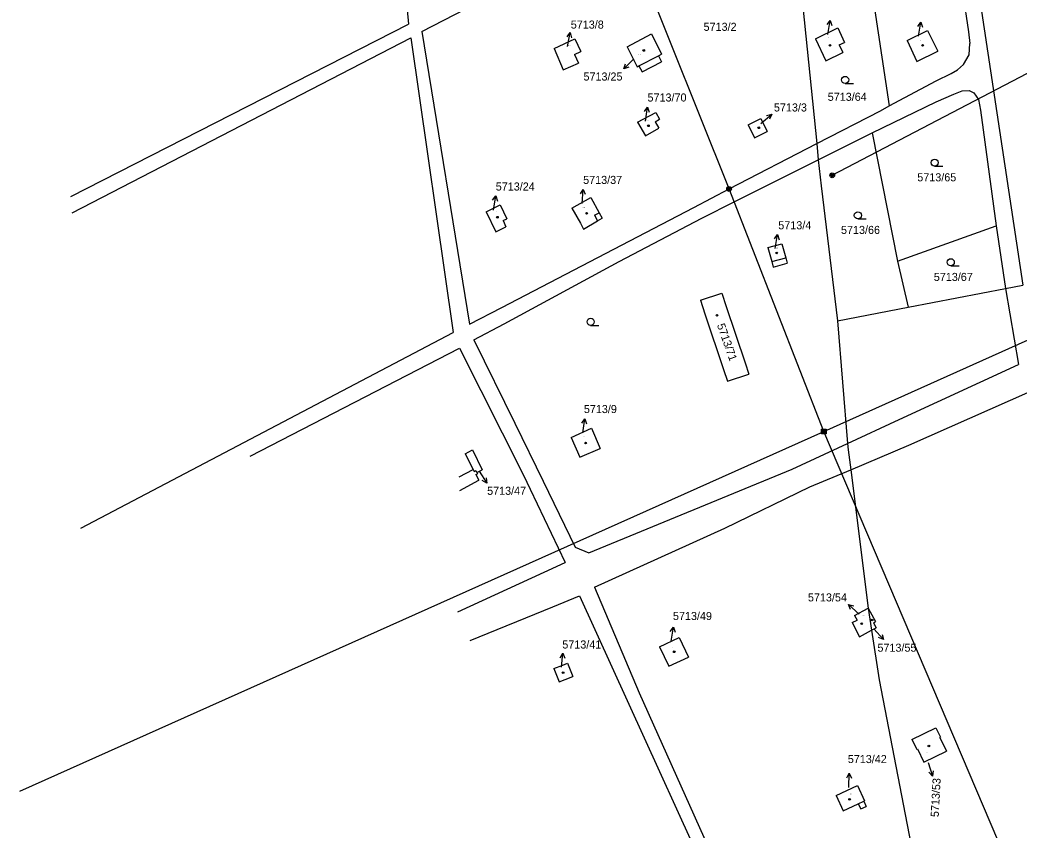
# Model space of a CAD drawing. Extents: x -735092 to -733385, y -1122435 to -1118992.
# Drawn here: x -734530.2 to -734319.7, y -1121420.4 to -1121249.7 of the extents above; entities that cross this region are included whole.
import ezdxf

# ---------------------------------------------------------------- set-up
doc = ezdxf.new("R2010")
doc.units = 0
for name, color, linetype in [('Vrstva 1', 7, 'Continuous'), ('Vrstva 12', 7, 'Continuous'), ('Vrstva 16', 7, 'Continuous'), ('Vrstva 18', 7, 'Continuous'), ('Vrstva 19', 7, 'Continuous'), ('Vrstva 25', 7, 'Continuous'), ('Vrstva 4', 7, 'Continuous')]:
    doc.layers.add(name, color=color, linetype=linetype)

msp = doc.modelspace()

# ---------------------------------------------------------------- linework, layer by layer
at = {"layer": 'Vrstva 1'}
for points in [[(-734339.29, -1121169.94), (-734318.83, -1121305.55)], [(-734333.92, -1121228.08), (-734330.31, -1121252.15)], [(-734351.7, -1121236.91), (-734347.03, -1121267.76)], [(-734365.53, -1121244.07), (-734362.31, -1121275.71)], [(-734362.57, -1121253.65), (-734357.87, -1121251.31)], [(-734357.87, -1121251.31), (-734356.45, -1121254.42)], [(-734417.66, -1121255.71), (-734413.26, -1121253.63)], [(-734413.26, -1121253.63), (-734412, -1121256.33)], [(-734402.24, -1121255.3), (-734397.14, -1121252.57)], [(-734397.14, -1121252.57), (-734394.99, -1121256.88)], [(-734362.57, -1121253.65), (-734360.41, -1121258.28)], [(-734343.21, -1121254.02), (-734338.94, -1121251.9)], [(-734338.94, -1121251.9), (-734336.78, -1121256.22)], [(-734330.31, -1121252.15), (-734330.04, -1121254.64)], [(-734417.66, -1121255.71), (-734415.71, -1121260.15)], [(-734402.24, -1121255.3), (-734400.12, -1121259.53)], [(-734357.55, -1121254.94), (-734356.45, -1121254.42)], [(-734357.55, -1121254.94), (-734356.78, -1121256.52)], [(-734343.21, -1121254.02), (-734341.18, -1121258.43)], [(-734330.16, -1121257.02), (-734330.04, -1121254.64)], [(-734413.32, -1121256.95), (-734412, -1121256.33)], [(-734413.32, -1121256.95), (-734412.49, -1121258.74)], [(-734395.68, -1121257.23), (-734394.99, -1121256.88)], [(-734395.68, -1121257.23), (-734395.03, -1121258.49)], [(-734360.41, -1121258.28), (-734356.78, -1121256.52)], [(-734341.18, -1121258.43), (-734336.78, -1121256.22)], [(-734331.39, -1121259.08), (-734330.16, -1121257.02)], [(-734415.71, -1121260.15), (-734412.49, -1121258.74)], [(-734400.12, -1121259.53), (-734399.76, -1121259.35)], [(-734399.76, -1121259.35), (-734399.12, -1121260.58)], [(-734399.12, -1121260.58), (-734395.03, -1121258.49)], [(-734332.61, -1121260.16), (-734331.39, -1121259.08)], [(-734337.15, -1121262.5), (-734333.96, -1121260.96)], [(-734333.96, -1121260.96), (-734332.61, -1121260.16)], [(-734347.03, -1121267.76), (-734337.15, -1121262.5)], [(-734337.1, -1121266.93), (-734333.42, -1121265.31)], [(-734333.42, -1121265.31), (-734331.61, -1121264.64)], [(-734331.61, -1121264.64), (-734330.18, -1121264.55)], [(-734330.18, -1121264.55), (-734329.17, -1121265.05)], [(-734329.17, -1121265.05), (-734328.19, -1121266.44)], [(-734350.61, -1121273.46), (-734337.1, -1121266.93)], [(-734348.87, -1121268.81), (-734347.03, -1121267.76)], [(-734328.19, -1121266.44), (-734327.75, -1121268.66)], [(-734400.04, -1121271.2), (-734396.18, -1121269.18)], [(-734396.18, -1121269.18), (-734395.41, -1121270.57)], [(-734376.78, -1121271.78), (-734374.05, -1121270.44)], [(-734374.05, -1121270.44), (-734372.71, -1121273.18)], [(-734362.31, -1121275.71), (-734348.87, -1121268.81)], [(-734327.75, -1121268.66), (-734324.5, -1121293.09)], [(-734400.04, -1121271.2), (-734398.42, -1121274.09)], [(-734398.42, -1121274.09), (-734395.59, -1121272.5)], [(-734396.33, -1121271.11), (-734395.41, -1121270.57)], [(-734396.33, -1121271.11), (-734395.59, -1121272.5)], [(-734376.78, -1121271.78), (-734375.44, -1121274.52)], [(-734375.44, -1121274.52), (-734372.71, -1121273.18)], [(-734361.96, -1121279.14), (-734350.61, -1121273.46)], [(-734350.61, -1121273.46), (-734345.24, -1121300.5)], [(-734362.31, -1121275.71), (-734361.96, -1121279.14)], [(-734361.96, -1121279.14), (-734361.39, -1121284.66)], [(-734361.39, -1121284.66), (-734357.89, -1121313.1)], [(-734413.91, -1121289.33), (-734409.88, -1121287.11)], [(-734409.88, -1121287.11), (-734408.16, -1121290.31)], [(-734431.97, -1121290.09), (-734429.03, -1121288.65)], [(-734429.03, -1121288.65), (-734427.61, -1121291.57)], [(-734413.91, -1121289.33), (-734412.12, -1121292.53)], [(-734431.97, -1121290.09), (-734429.91, -1121294.31)], [(-734408.51, -1121291.99), (-734407.55, -1121291.44)], [(-734408.16, -1121290.31), (-734407.55, -1121291.44)], [(-734429.91, -1121294.31), (-734427.84, -1121293.3)], [(-734428.4, -1121291.96), (-734427.61, -1121291.57)], [(-734428.4, -1121291.96), (-734427.84, -1121293.3)], [(-734412.12, -1121292.53), (-734411.45, -1121293.73)], [(-734411.45, -1121293.73), (-734408.51, -1121291.99)], [(-734345.24, -1121300.5), (-734324.5, -1121293.09)], [(-734324.5, -1121293.09), (-734322.51, -1121306.27)], [(-734372.61, -1121297.66), (-734369.66, -1121296.83)], [(-734372.61, -1121297.66), (-734371.78, -1121300.61)], [(-734369.66, -1121296.83), (-734368.83, -1121299.78)], [(-734368.83, -1121299.78), (-734368.5, -1121300.95)], [(-734371.78, -1121300.61), (-734371.45, -1121301.78)], [(-734371.45, -1121301.78), (-734368.5, -1121300.95)], [(-734345.24, -1121300.5), (-734342.99, -1121310.22)], [(-734342.99, -1121310.22), (-734322.51, -1121306.27)], [(-734322.51, -1121306.27), (-734318.83, -1121305.55)], [(-734386.83, -1121308.74), (-734382.32, -1121307.24)], [(-734382.32, -1121307.24), (-734381.39, -1121310.08)], [(-734386.83, -1121308.74), (-734385.88, -1121311.58)], [(-734381.39, -1121310.08), (-734377.41, -1121321.91)], [(-734357.89, -1121313.1), (-734342.99, -1121310.22)], [(-734385.88, -1121311.58), (-734381.92, -1121323.34)], [(-734357.89, -1121313.1), (-734355.78, -1121338.91)], [(-734377.41, -1121321.91), (-734376.63, -1121324.29)], [(-734381.92, -1121323.34), (-734381.1, -1121325.79)], [(-734381.1, -1121325.79), (-734376.63, -1121324.29)], [(-734414.08, -1121337.64), (-734409.79, -1121335.72)], [(-734409.79, -1121335.72), (-734407.94, -1121339.98)], [(-734414.08, -1121337.64), (-734412.2, -1121341.85)], [(-734412.2, -1121341.85), (-734407.94, -1121339.98)], [(-734355.78, -1121338.91), (-734355.67, -1121340.27)], [(-734436.43, -1121341.09), (-734434.87, -1121340.26)], [(-734436.43, -1121341.09), (-734434.72, -1121344.41)], [(-734434.87, -1121340.26), (-734432.82, -1121344.48)], [(-734355.67, -1121340.27), (-734355.14, -1121344.46)], [(-734434.72, -1121344.41), (-734434.5, -1121344.83)], [(-734434.5, -1121344.83), (-734434.12, -1121344.63)], [(-734434.15, -1121345.49), (-734433.78, -1121345.31)], [(-734434.15, -1121345.49), (-734433.5, -1121346.65)], [(-734434.12, -1121344.63), (-734433.92, -1121345.04)], [(-734433.92, -1121345.04), (-734432.82, -1121344.48)], [(-734433.92, -1121345.04), (-734433.78, -1121345.31)], [(-734355.14, -1121344.46), (-734351.46, -1121373.64)], [(-734437.52, -1121348.84), (-734433.5, -1121346.65)], [(-734354.31, -1121375.19), (-734351.46, -1121373.64)], [(-734351.46, -1121373.64), (-734350.74, -1121378.29)], [(-734351.46, -1121373.64), (-734349.89, -1121376.46)], [(-734354.31, -1121375.19), (-734353.78, -1121376.14)], [(-734354.84, -1121376.69), (-734353.78, -1121376.14)], [(-734354.84, -1121376.69), (-734353.29, -1121379.67)], [(-734350.74, -1121378.29), (-734349.77, -1121377.77)], [(-734350.36, -1121376.72), (-734349.89, -1121376.46)], [(-734350.36, -1121376.72), (-734349.77, -1121377.77)], [(-734395.41, -1121381.79), (-734391.27, -1121379.81)], [(-734391.27, -1121379.81), (-734389.31, -1121383.95)], [(-734353.29, -1121379.67), (-734350.74, -1121378.29)], [(-734350.74, -1121378.29), (-734349.15, -1121388.78)], [(-734395.41, -1121381.79), (-734393.48, -1121385.9)], [(-734393.48, -1121385.9), (-734389.31, -1121383.95)], [(-734417.7, -1121386.38), (-734415.78, -1121385.62)], [(-734415.78, -1121385.62), (-734414.84, -1121385.25)], [(-734414.84, -1121385.25), (-734413.71, -1121388.05)], [(-734417.7, -1121386.38), (-734416.59, -1121389.18)], [(-734415.31, -1121388.68), (-734413.71, -1121388.05)], [(-734416.59, -1121389.18), (-734415.31, -1121388.68)], [(-734349.15, -1121388.78), (-734339.7, -1121437.49)], [(-734342.26, -1121401.29), (-734337.18, -1121398.85)], [(-734337.18, -1121398.85), (-734336.21, -1121400.82)], [(-734336.35, -1121400.89), (-734336.21, -1121400.82)], [(-734336.35, -1121400.89), (-734334.93, -1121403.8)], [(-734342.26, -1121401.29), (-734341.22, -1121403.39)], [(-734341.22, -1121403.39), (-734341.09, -1121403.32)], [(-734341.09, -1121403.32), (-734339.7, -1121406.13)], [(-734339.7, -1121406.13), (-734334.93, -1121403.8)], [(-734358.23, -1121413.13), (-734353.72, -1121411.04)], [(-734353.72, -1121411.04), (-734352.26, -1121414.28)], [(-734358.23, -1121413.13), (-734356.76, -1121416.38)], [(-734356.76, -1121416.38), (-734353.53, -1121414.88)], [(-734353.53, -1121414.88), (-734353.03, -1121415.96)], [(-734353.03, -1121415.96), (-734351.85, -1121415.42)], [(-734352.36, -1121414.33), (-734352.26, -1121414.28)], [(-734352.36, -1121414.33), (-734351.85, -1121415.42)]]:
    msp.add_lwpolyline(points, dxfattribs=at)
at = {"layer": 'Vrstva 12'}
for points in [[(-734359.03, -1121282.41), (-734007.75, -1121098.86)], [(-734380.76, -1121285.29), (-734399.23, -1121239.12)], [(-734360.81, -1121336.42), (-734230.19, -1121277.82)], [(-734360.81, -1121336.42), (-734380.76, -1121285.29)], [(-734530.23, -1121412.21), (-734360.81, -1121336.42)], [(-734319.48, -1121433.41), (-734360.81, -1121336.42)]]:
    msp.add_lwpolyline(points, dxfattribs=at)
at = {"layer": 'Vrstva 25'}
for points in [[(-734360.121, -1121250.654), (-734359.454, -1121249.757), (-734359.138, -1121250.829)], [(-734359.98, -1121252.71), (-734359.454, -1121249.757)], [(-734340.985, -1121251.045), (-734340.325, -1121250.143), (-734340.001, -1121251.213)], [(-734340.83, -1121253.1), (-734340.325, -1121250.143)], [(-734414.933, -1121253.21), (-734414.237, -1121252.336), (-734413.956, -1121253.418)], [(-734414.86, -1121255.27), (-734414.237, -1121252.336)], [(-734400.82, -1121257.88), (-734402.97, -1121259.971)], [(-734401.905, -1121259.632), (-734402.97, -1121259.971), (-734402.602, -1121258.915)], [(-734356.31, -1121263.06), (-734354.56, -1121263.06)], [(-734398.572, -1121268.979), (-734397.932, -1121268.063), (-734397.584, -1121269.125)], [(-734398.37, -1121271.03), (-734397.932, -1121268.063)], [(-734374.06, -1121271.51), (-734371.786, -1121269.554)], [(-734372.87, -1121269.827), (-734371.786, -1121269.554), (-734372.218, -1121270.585)], [(-734337.44, -1121280.49), (-734335.69, -1121280.49)], [(-734430.601, -1121287.678), (-734429.957, -1121286.765), (-734429.614, -1121287.829)], [(-734430.41, -1121289.73), (-734429.957, -1121286.765)], [(-734412.102, -1121286.329), (-734411.531, -1121285.369), (-734411.105, -1121286.402)], [(-734411.75, -1121288.36), (-734411.531, -1121285.369)], [(-734353.63, -1121291.6), (-734351.88, -1121291.6)], [(-734371.21, -1121295.803), (-734370.539, -1121294.91), (-734370.228, -1121295.984)], [(-734371.08, -1121297.86), (-734370.539, -1121294.91)], [(-734334.05, -1121301.49), (-734332.3, -1121301.49)], [(-734409.95, -1121314.04), (-734408.2, -1121314.04)], [(-734411.839, -1121334.67), (-734411.203, -1121333.751), (-734410.85, -1121334.812)], [(-734411.63, -1121336.72), (-734411.203, -1121333.751)], [(-734361.31, -1121335.92), (-734360.31, -1121335.92), (-734360.31, -1121336.92), (-734361.31, -1121336.92), (-734361.31, -1121335.92)], [(-734361.11, -1121336.12), (-734360.51, -1121336.12), (-734360.51, -1121336.72), (-734361.11, -1121336.72), (-734361.11, -1121336.12)], [(-734360.91, -1121336.32), (-734360.71, -1121336.32), (-734360.71, -1121336.52), (-734360.91, -1121336.52), (-734360.91, -1121336.32)], [(-734433.43, -1121344.76), (-734431.85, -1121347.309)], [(-734431.952, -1121346.196), (-734431.85, -1121347.309), (-734432.802, -1121346.723)], [(-734353.36, -1121374.89), (-734355.582, -1121372.875)], [(-734355.177, -1121373.917), (-734355.582, -1121372.875), (-734354.505, -1121373.177)], [(-734393.156, -1121378.579), (-734392.517, -1121377.662), (-734392.167, -1121378.724)], [(-734392.95, -1121380.63), (-734392.517, -1121377.662)], [(-734350.23, -1121378.01), (-734348.239, -1121380.253)], [(-734348.529, -1121379.173), (-734348.239, -1121380.253), (-734349.277, -1121379.837)], [(-734416.408, -1121384.079), (-734415.836, -1121383.119), (-734415.412, -1121384.154)], [(-734416.06, -1121386.11), (-734415.836, -1121383.119)], [(-734338.83, -1121406.17), (-734337.903, -1121409.023)], [(-734355.967, -1121409.418), (-734355.442, -1121408.432), (-734354.968, -1121409.444)], [(-734355.52, -1121411.43), (-734355.442, -1121408.432)], [(-734337.737, -1121407.917), (-734337.903, -1121409.023), (-734338.688, -1121408.226)]]:
    msp.add_lwpolyline(points, dxfattribs=at)
for centre, radius in [((-734359.51, -1121255.02), 0.175), ((-734339.97, -1121255.02), 0.175), ((-734398.74, -1121256.09), 0.175), ((-734356.31, -1121262.31), 0.75), ((-734397.77, -1121271.97), 0.175), ((-734374.51, -1121272.39), 0.175), ((-734337.44, -1121279.74), 0.75), ((-734359.03, -1121282.41), 0.5), ((-734359.03, -1121282.41), 0.3), ((-734359.03, -1121282.41), 0.15), ((-734380.76, -1121285.29), 0.5), ((-734380.76, -1121285.29), 0.3), ((-734380.76, -1121285.29), 0.15), ((-734429.6, -1121291.25), 0.175), ((-734410.8, -1121290.41), 0.175), ((-734353.63, -1121290.85), 0.75), ((-734370.73, -1121298.77), 0.175), ((-734334.05, -1121300.74), 0.75), ((-734409.95, -1121313.29), 0.75), ((-734383.32, -1121311.91), 0.175), ((-734411.01, -1121338.84), 0.175), ((-734352.82, -1121376.91), 0.175), ((-734350.63, -1121376.14), 0.175), ((-734392.33, -1121382.84), 0.175), ((-734415.75, -1121387.23), 0.175), ((-734338.66, -1121402.69), 0.175), ((-734355.38, -1121413.93), 0.175)]:
    msp.add_circle(centre, radius, dxfattribs=at)
at = {"layer": 'Vrstva 4'}
for points in [[(-734455.44, -1121173.91), (-734448.33, -1121250.54)], [(-734445.52, -1121252.13), (-734369.33, -1121212.74)], [(-734519.51, -1121286.85), (-734448.33, -1121250.54)], [(-734519.22, -1121290.32), (-734447.88, -1121253.42)], [(-734447.88, -1121253.42), (-734438.96, -1121315.56)], [(-734445.52, -1121252.13), (-734435.47, -1121313.77)], [(-734399.76, -1121259.35), (-734395.68, -1121257.23)], [(-734380.76, -1121285.29), (-734362.31, -1121275.71)], [(-734379.54, -1121287.95), (-734361.96, -1121279.14)], [(-734388.19, -1121289.16), (-734380.76, -1121285.29)], [(-734428.7, -1121310.24), (-734388.19, -1121289.16)], [(-734386.54, -1121291.46), (-734379.54, -1121287.95)], [(-734409.13, -1121290.84), (-734408.16, -1121290.31)], [(-734409.13, -1121290.84), (-734408.51, -1121291.99)], [(-734403.93, -1121300.6), (-734386.54, -1121291.46)], [(-734371.78, -1121300.61), (-734368.83, -1121299.78)], [(-734428.21, -1121313.7), (-734403.93, -1121300.6)], [(-734322.51, -1121306.27), (-734319.78, -1121322.32)], [(-734435.47, -1121313.77), (-734428.7, -1121310.24)], [(-734342.88, -1121339.31), (-734279.23, -1121311.1)], [(-734434.54, -1121317.12), (-734428.21, -1121313.7)], [(-734517.43, -1121356.77), (-734438.96, -1121315.56)], [(-734481.72, -1121341.6), (-734437.56, -1121318.87)], [(-734437.56, -1121318.87), (-734424.13, -1121345.62)], [(-734434.54, -1121317.12), (-734425.93, -1121334.65)], [(-734344.9, -1121333.86), (-734319.78, -1121322.32)], [(-734425.93, -1121334.65), (-734419.95, -1121346.84)], [(-734355.78, -1121338.91), (-734344.9, -1121333.86)], [(-734367.49, -1121344.35), (-734355.78, -1121338.91)], [(-734355.14, -1121344.46), (-734342.88, -1121339.31)], [(-734437.68, -1121345.94), (-734434.72, -1121344.41)], [(-734424.13, -1121345.62), (-734422.67, -1121348.54)], [(-734410.34, -1121362), (-734367.49, -1121344.35)], [(-734363.77, -1121348.09), (-734355.14, -1121344.46)], [(-734419.95, -1121346.84), (-734413.18, -1121360.8)], [(-734381.66, -1121356.75), (-734363.77, -1121348.09)], [(-734422.67, -1121348.54), (-734415.3, -1121364)], [(-734409.14, -1121369.25), (-734381.66, -1121356.75)], [(-734413.18, -1121360.8), (-734410.34, -1121362)], [(-734419.78, -1121366.05), (-734415.3, -1121364)], [(-734437.96, -1121374.4), (-734419.78, -1121366.05)], [(-734409.14, -1121369.25), (-734399.71, -1121391.47)], [(-734417.9, -1121373.35), (-734412.3, -1121371.06)], [(-734412.3, -1121371.06), (-734374.98, -1121452.93)], [(-734435.35, -1121380.48), (-734417.9, -1121373.35)], [(-734399.71, -1121391.47), (-734372.45, -1121452.34)], [(-734353.53, -1121414.88), (-734352.36, -1121414.33)]]:
    msp.add_lwpolyline(points, dxfattribs=at)

# ---------------------------------------------------------------- texts
at = {"layer": 'Vrstva 16'}
for s, p in [('5713/8', (-734414.14, -1121251.49)), ('5713/2', (-734386.147, -1121251.96)), ('5713/25', (-734411.457, -1121262.44)), ('5713/70', (-734397.96, -1121266.86)), ('5713/3', (-734371.32, -1121268.96)), ('5713/37', (-734411.53, -1121284.23)), ('5713/24', (-734429.95, -1121285.62)), ('5713/4', (-734370.4, -1121293.79)), ('5713/9', (-734411.38, -1121332.52)), ('5713/47', (-734431.77, -1121349.75)), ('5713/54', (-734364.147, -1121372.22)), ('5713/49', (-734392.6, -1121376.14)), ('5713/41', (-734415.92, -1121382.15)), ('5713/55', (-734349.5, -1121382.82)), ('5713/42', (-734355.75, -1121406.29))]:
    msp.add_text(s, height=1.7, dxfattribs=at).set_placement(p)
msp.add_text('5713/53', height=1.7, rotation=87.00069, dxfattribs=at).set_placement((-734336.595, -1121417.714))
at = {"layer": 'Vrstva 18'}
for s, height, p in [('5713/8', 0.1, (-734414.68, -1121255.15)), ('5713/64', 1.7, (-734359.98, -1121266.71)), ('5713/65', 1.7, (-734341.1, -1121283.68)), ('5713/66', 1.7, (-734357.18, -1121294.77)), ('5713/67', 1.7, (-734337.62, -1121304.68)), ('5713/47', 0.1, (-734433.69, -1121343.82))]:
    msp.add_text(s, height=height, dxfattribs=at).set_placement(p)
at = {"layer": 'Vrstva 19'}
for s, p in [('5713/51', (-734359.95, -1121253.45)), ('5713/38', (-734340.81, -1121253.98)), ('5713/25', (-734399.95, -1121257.03)), ('5713/70', (-734398.19, -1121270.99)), ('5713/3', (-734374.03, -1121271.45)), ('5713/37', (-734411.63, -1121289.22)), ('5713/24', (-734430.29, -1121290.07)), ('5713/4', (-734370.9, -1121297.77)), ('5713/9', (-734411.57, -1121337.51)), ('5713/54', (-734352.68, -1121375.12)), ('5713/55', (-734350.44, -1121377.35)), ('5713/49', (-734392.98, -1121381.98)), ('5713/41', (-734415.88, -1121386.21)), ('5713/53', (-734339.25, -1121404.05)), ('5713/42', (-734355.36, -1121412.86))]:
    msp.add_text(s, height=0.1, dxfattribs=at).set_placement(p)
msp.add_text('5713/71', height=1.7, rotation=289.4023, dxfattribs=at).set_placement((-734383.355, -1121313.972))

doc.saveas('drawing.dxf')
